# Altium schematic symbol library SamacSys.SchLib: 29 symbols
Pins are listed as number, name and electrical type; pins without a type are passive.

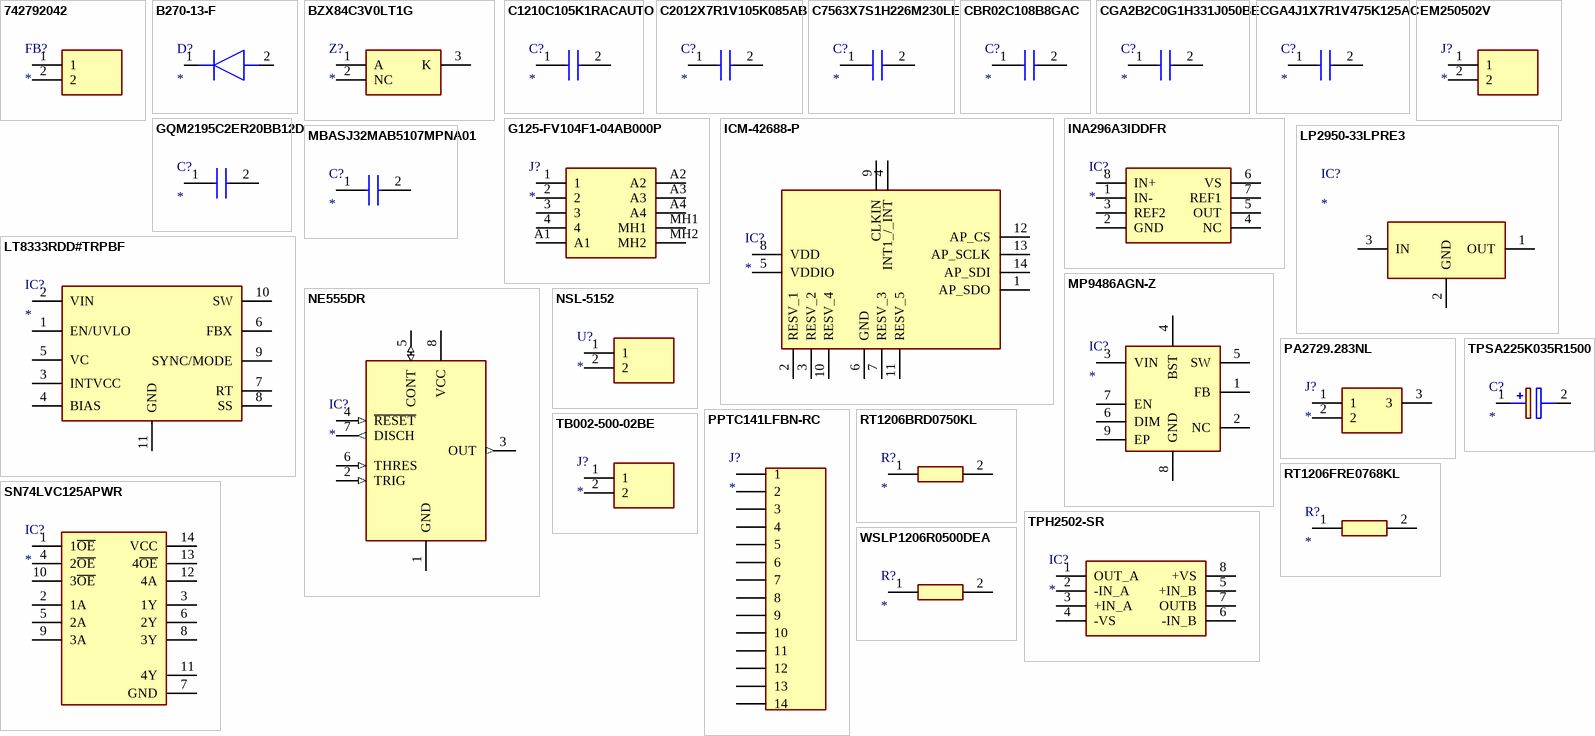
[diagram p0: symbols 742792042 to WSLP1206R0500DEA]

## 742792042
designator FB?
Ferrite Bead; Manufacturer_Name: Wurth Elektronik; Manufacturer_Part_Number: 742792042
footprint BEADC2012X90N
pins: 1, 2

## B270-13-F
designator D?
Diode; Manufacturer_Name: Diodes Incorporated; Manufacturer_Part_Number: B270-13-F
footprint DIOM5336X250N
pins: 1 K, 2 A

## BZX84C3V0LT1G
designator Z?
Zener Diode; Manufacturer_Name: onsemi; Manufacturer_Part_Number: BZX84C3V0LT1G
footprint SOT96P237X111-3N
pins: 1 A, 2 NC, 3 K

## C1210C105K1RACAUTO
designator C?
Capacitor; Manufacturer_Name: Yageo Group; Manufacturer_Part_Number: C1210C105K1RACAUTO
footprint C1210
pins: 1, 2

## C2012X7R1V105K085AB
designator C?
Capacitor; Manufacturer_Name: TDK; Manufacturer_Part_Number: C2012X7R1V105K085AB
footprint C2012_Commercial
pins: 1, 2

## C7563X7S1H226M230LE
designator C?
Capacitor; Manufacturer_Name: TDK; Manufacturer_Part_Number: C7563X7S1H226M230LE
footprint CAPC7563X250N
pins: 1, 2

## CBR02C108B8GAC
designator C?
Capacitor; Manufacturer_Name: Yageo Group; Manufacturer_Part_Number: CBR02C108B8GAC
footprint CAPC0603X33N
pins: 1, 2

## CGA2B2C0G1H331J050BE
designator C?
Capacitor; Manufacturer_Name: TDK; Manufacturer_Part_Number: CGA2B2C0G1H331J050BE
footprint CAPC1005X55N
pins: 1, 2

## CGA4J1X7R1V475K125AC
designator C?
Capacitor; Manufacturer_Name: TDK; Manufacturer_Part_Number: CGA4J1X7R1V475K125AC
footprint CGA4J2NP01H223J125AA
pins: 1, 2

## EM250502V
designator J?
Connector; Manufacturer_Name: Eaton; Manufacturer_Part_Number: EM250502V
footprint EM250502V
pins: 1, 2

## G125-FV104F1-04AB000P
designator J?
Connector; Manufacturer_Name: Harwin; Manufacturer_Part_Number: G125-FV104F1-04AB000P
footprint G125FV104F104AB000P
pins: 1, 2, 3, 4, A1, A2, A3, A4, MH1, MH2

## GQM2195C2ER20BB12D
designator C?
Capacitor; Manufacturer_Name: Murata Electronics; Manufacturer_Part_Number: GQM2195C2ER20BB12D
footprint GQM219
pins: 1, 2

## ICM-42688-P
designator IC?
Integrated Circuit; Manufacturer_Name: TDK; Manufacturer_Part_Number: ICM-42688-P
footprint IIM42352
pins: 1 AP_SDO, 2 RESV_1, 3 RESV_2, 4 INT1_/_INT, 5 VDDIO (power), 6 GND (power), 7 RESV_3, 8 VDD (power), 9 CLKIN, 10 RESV_4, 11 RESV_5, 12 AP_CS, 13 AP_SCLK, 14 AP_SDI

## INA296A3IDDFR
designator IC?
Integrated Circuit; Manufacturer_Name: Texas Instruments; Manufacturer_Part_Number: INA296A3IDDFR
footprint SOT65P280X110-8N
pins: 1 IN-, 2 GND, 3 REF2, 4 NC, 5 OUT, 6 VS, 7 REF1, 8 IN+

## LP2950-33LPRE3
designator IC?
Integrated Circuit; Manufacturer_Name: Texas Instruments; Manufacturer_Part_Number: LP2950-33LPRE3
footprint TL431CLPM
pins: 1 OUT (power), 2 GND, 3 IN (power)

## LT8333RDD#TRPBF
designator IC?
Integrated Circuit; Manufacturer_Name: Analog Devices; Manufacturer_Part_Number: LT8333RDD#TRPBF
footprint SON50P300X300X80-11N-D
pins: 1 EN/UVLO, 2 VIN, 3 INTVCC, 4 BIAS, 5 VC, 6 FBX, 7 RT, 8 SS, 9 SYNC/MODE, 10 SW, 11 GND

## MBASJ32MAB5107MPNA01
designator C?
Capacitor; Manufacturer_Name: TAIYO YUDEN; Manufacturer_Part_Number: MBASJ32MAB5107MPNA01
footprint MBASx32x
pins: 1, 2

## MP9486AGN-Z
designator IC?
Integrated Circuit; Manufacturer_Name: Monolithic Power Systems (MPS); Manufacturer_Part_Number: MP9486AGN-Z
footprint SOIC127P600X170-9N
pins: 1 FB, 2 NC, 3 VIN, 4 BST, 5 SW, 6 DIM, 7 EN, 8 GND, 9 EP

## NE555DR
designator IC?
Integrated Circuit; Manufacturer_Name: Texas Instruments; Manufacturer_Part_Number: NE555DR
footprint SOIC127P600X175-8N
pins: 1 GND (power), 2 TRIG (in), 3 OUT (out), 4 ~{RESET} (in), 5 CONT (io), 6 THRES (in), 7 DISCH (out), 8 VCC (power)

## NSL-5152
designator U?
Undefined or Miscellaneous; Manufacturer_Name: ADVANCED PHOTONIX
footprint NSL5152
pins: 1, 2

## PA2729.283NL
designator J?
Connector; Manufacturer_Name: Yageo Group; Manufacturer_Part_Number: PA2729.283NL
footprint PA2729283NL
pins: 1, 2, 3

## PPTC141LFBN-RC
designator J?
Connector; Manufacturer_Name: Sullins; Manufacturer_Part_Number: PPTC141LFBN-RC
footprint RHDR14W80P0X254_1X14_3606X254X850P
pins: 1, 2, 3, 4, 5, 6, 7, 8, 9, 10, 11, 12, 13, 14

## RT1206BRD0750KL
designator R?
Resistor; Manufacturer_Name: Yageo Group; Manufacturer_Part_Number: RT1206BRD0750KL
footprint CAPC3116X65N
pins: 1, 2

## RT1206FRE0768KL
designator R?
Resistor; Manufacturer_Name: Yageo Group; Manufacturer_Part_Number: RT1206FRE0768KL
footprint RESC3116X65N
pins: 1, 2

## SN74LVC125APWR
designator IC?
Integrated Circuit; Manufacturer_Name: Texas Instruments; Manufacturer_Part_Number: SN74LVC125APWR
footprint SN74LVC125APWR
pins: 1 1~{OE}, 2 1A, 3 1Y, 4 2~{OE}, 5 2A, 6 2Y, 7 GND, 8 3Y, 9 3A, 10 3~{OE}, 11 4Y, 12 4A, 13 4~{OE}, 14 VCC

## TB002-500-02BE
designator J?
Connector; Manufacturer_Name: Same Sky; Manufacturer_Part_Number: TB002-500-02BE
footprint TB002-500-02BE
pins: 1, 2

## TPH2502-SR
designator IC?
Integrated Circuit; Manufacturer_Name: 3Peak Incorporated; Manufacturer_Part_Number: TPH2502-SR
footprint SOIC127P600X175-8N
pins: 1 OUT_A, 2 -IN_A, 3 +IN_A, 4 -VS, 5 +IN_B, 6 -IN_B, 7 OUTB, 8 +VS

## TPSA225K035R1500
designator C?
Capacitor Polarised; Manufacturer_Name: Kyocera AVX; Manufacturer_Part_Number: TPSA225K035R1500
footprint CAPPM3216X180N
pins: 1 + (power), 2 - (power)

## WSLP1206R0500DEA
designator R?
Resistor; Manufacturer_Name: Vishay; Manufacturer_Part_Number: WSLP1206R0500DEA
footprint RESC3216X89N
pins: 1, 2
